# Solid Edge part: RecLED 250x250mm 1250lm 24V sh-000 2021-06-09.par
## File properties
Author: radoslaw.kuczynski
Template: iso metric part.par
Last saved by: radoslaw.kuczynski
Revision: 2
Application: Solid Edge
Gęstość: 0,000 kg/m^3
Dokładność: 0,990
Username: radoslaw.kuczynski
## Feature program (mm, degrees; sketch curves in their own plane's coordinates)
body "unnamed Body 1"
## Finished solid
Body 1: solid body, 1861 faces, 4824 edges, 3098 vertices.
  Faces by surface: plane 1360, cylinder 233, spline 160, cone 52, torus 22, sphere 20, spun 14
  Edges by curve: line 3736, curve on surface 564, circle 304, ellipse 132, spline 76, intersection 12
Bounding box of the edges (mm; curved faces can reach further): 249.000 x 4.450 x 249.000, from (-124.5, -3.45, -124.5) to (124.5, 1, 124.5).
Cylindrical faces by radius (mm): R0.2 x78, R0.2002 x4, R0.2169 x6, R0.25 x24, R0.3 x4, R0.3373 x6, R0.4 x16, R0.4006 x4, R0.4008 x4, R0.525 x4, R0.6 x24, R1 x14, R1.0894 x4, R1.1 x28, R1.5 x8, R2.25 x5
Conical faces (half-angle, radius in mm at the cone's reference point): 0.5 deg R0.5056 x8, 0.5 deg R1.0082 x8, 1 deg R0.5511 x4, 10 deg R0.2132 x4, 10 deg R0.4132 x4, 18.4844 deg R1.0657 x8, 27.363 deg R0.6214 x4, 45 deg R0.575 x4, 45 deg R0.625 x8
Toroidal faces (ring radius, tube radius in mm): R0.1 r0.2 x2, R0.8 r0.2 x8, R0.8522 r0.3 x4, R0.9002 r0.2 x2, R0.9018 r0.2 x2, R1.3 r0.2 x4
Spherical faces by radius (mm): R0.2 x16, R0.6 x4
Planar faces by outward normal: +x 155, +y 15, +z 156, -x 155, -y 231, -z 156, oblique 492
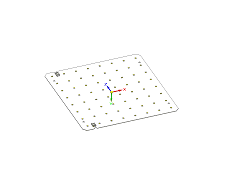
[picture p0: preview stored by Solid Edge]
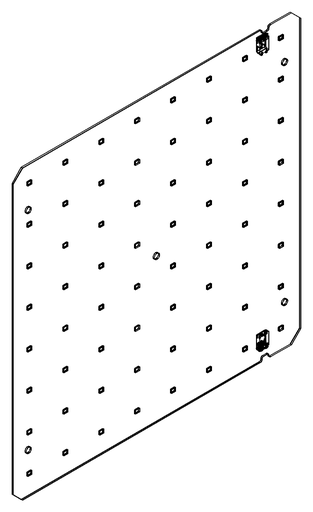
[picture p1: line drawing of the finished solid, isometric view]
